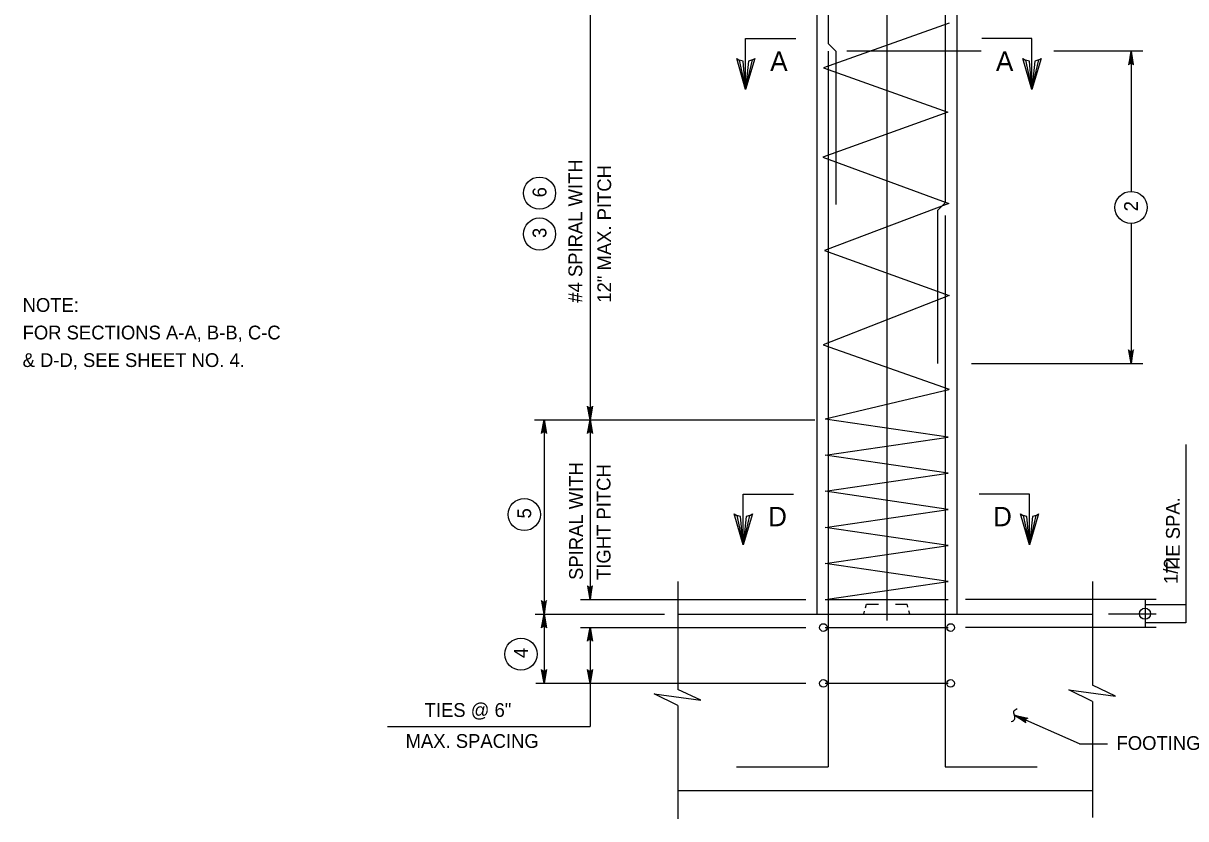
# Model space of a CAD drawing. Extents: x 646165 to 651486, y 296916 to 299292.
# Drawn here: x 648585.6 to 648838.6, y 297806.4 to 297979.6 of the extents above; entities that cross this region are included whole.
import ezdxf

# ---------------------------------------------------------------- set-up
doc = ezdxf.new("R2010")
doc.units = 0
for name, color, linetype in [('1', 7, 'Continuous'), ('50', 7, 'Continuous'), ('51', 7, 'Continuous'), ('52', 7, 'Continuous'), ('53', 7, 'Continuous'), ('54', 7, 'Continuous'), ('57', 7, 'Continuous')]:
    doc.layers.add(name, color=color, linetype=linetype)

msp = doc.modelspace()

# ---------------------------------------------------------------- linework, layer by layer
at = {"layer": '1'}
for p, q in [((648742.83, 297965.16), (648742.83, 297976.23)), ((648742.83, 297976.23), (648753.76, 297976.23)), ((648805.15, 297976.23), (648794.23, 297976.23)), ((648805.15, 297965.16), (648805.15, 297976.23)), ((648742.3, 297877.08), (648753.22, 297877.08)), ((648742.3, 297866.01), (648742.3, 297877.08)), ((648804.62, 297877.08), (648793.69, 297877.08)), ((648804.62, 297866.01), (648804.62, 297877.08))]:
    msp.add_line(p, q, dxfattribs=at)
for points in [[(648744.3, 297971.58), (648743.46, 297971.34), (648742.83, 297965.16), (648744.3, 297971.58), (648744.82, 297971.91), (648742.83, 297965.16), (648742.27, 297971.34), (648741.44, 297971.56), (648742.83, 297965.16), (648740.88, 297971.91), (648741.44, 297971.56)], [(648806.62, 297971.58), (648805.77, 297971.34), (648805.15, 297965.16), (648806.62, 297971.58), (648807.14, 297971.91), (648805.15, 297965.16), (648804.59, 297971.34), (648803.76, 297971.56), (648805.15, 297965.16), (648803.2, 297971.91), (648803.76, 297971.56)], [(648743.77, 297872.43), (648742.92, 297872.19), (648742.3, 297866.01), (648743.77, 297872.43), (648744.29, 297872.76), (648742.3, 297866.01), (648741.74, 297872.19), (648740.91, 297872.41), (648742.3, 297866.01), (648740.35, 297872.76), (648740.91, 297872.41)], [(648806.09, 297872.43), (648805.24, 297872.19), (648804.62, 297866.01), (648806.09, 297872.43), (648806.6, 297872.76), (648804.62, 297866.01), (648804.06, 297872.19), (648803.22, 297872.41), (648804.62, 297866.01), (648802.67, 297872.76), (648803.22, 297872.41)]]:
    msp.add_lwpolyline(points, dxfattribs=at)
at = {"layer": '50'}
msp.add_line((648773.54, 298034.59), (648773.54, 297849.57), dxfattribs=at)
at = {"layer": '51'}
for p, q in [((648758.31, 298027.15), (648758.31, 297850.9)), ((648788.77, 298027.15), (648788.77, 297850.9)), ((648768.91, 297852.34), (648769.11, 297853.1)), ((648769.11, 297853.1), (648771.75, 297853.1)), ((648775.48, 297853.1), (648777.98, 297853.1)), ((648778.15, 297852.43), (648777.98, 297853.1)), ((648728.08, 297850.9), (648818.35, 297850.9)), ((648768.54, 297850.9), (648768.71, 297851.57)), ((648778.54, 297850.9), (648778.34, 297851.68)), ((648728.08, 297812.57), (648818.35, 297812.57))]:
    msp.add_line(p, q, dxfattribs=at)
at = {"layer": '52'}
for p, q in [((648708.95, 297985.72), (648708.95, 297893.24)), ((648794.08, 297973.48), (648764.83, 297973.48)), ((648829.26, 297973.48), (648809.89, 297973.48)), ((648826.72, 297973.48), (648826.72, 297942.98)), ((648826.72, 297935.98), (648826.72, 297905.48)), ((648791.99, 297905.48), (648829.26, 297905.48)), ((648696.83, 297893.24), (648757.9, 297893.24)), ((648698.95, 297893.24), (648698.95, 297850.9)), ((648708.95, 297893.24), (648708.95, 297854.14)), ((648838.62, 297887.9), (648838.62, 297849.06)), ((648728.08, 297858.06), (648728.08, 297834.53)), ((648818.35, 297858.06), (648818.35, 297835.45)), ((648706.86, 297854.14), (648755.95, 297854.14)), ((648832.2, 297854.14), (648790.66, 297854.14)), ((648829.82, 297854.14), (648829.82, 297848.03)), ((648838.62, 297852.94), (648829.9, 297852.94)), ((648697.01, 297850.9), (648725.16, 297850.9)), ((648698.95, 297850.9), (648698.95, 297835.9)), ((648832.2, 297850.9), (648821.81, 297850.9)), ((648706.86, 297848.03), (648755.95, 297848.03)), ((648708.95, 297848.03), (648708.95, 297826.49)), ((648832.2, 297848.03), (648790.66, 297848.03)), ((648838.62, 297849.06), (648829.9, 297849.06)), ((648697.15, 297835.9), (648755.95, 297835.9)), ((648728.08, 297831.01), (648728.08, 297806.39)), ((648818.35, 297831.93), (648818.35, 297806.68)), ((648815.49, 297822.72), (648801.32, 297828.95)), ((648664.84, 297826.49), (648708.95, 297826.49)), ((648815.49, 297822.72), (648821.58, 297822.72))]:
    msp.add_line(p, q, dxfattribs=at)
for points in [[(648826.72, 297973.48), (648826.16, 297970.5), (648826.24, 297970.61), (648826.32, 297970.73), (648826.42, 297970.79), (648826.52, 297970.85), (648826.62, 297970.86), (648826.72, 297970.88), (648826.82, 297970.86), (648826.92, 297970.85), (648827.02, 297970.79), (648827.12, 297970.73), (648827.2, 297970.61), (648827.28, 297970.5), (648826.72, 297973.48), (648827.2, 297970.61), (648827.12, 297970.73), (648826.72, 297973.48), (648827.02, 297970.79), (648826.92, 297970.85), (648826.72, 297973.48), (648826.82, 297970.86), (648826.72, 297970.88), (648826.72, 297973.48), (648826.62, 297970.86), (648826.52, 297970.85), (648826.72, 297973.48), (648826.42, 297970.79), (648826.32, 297970.73), (648826.72, 297973.48), (648826.24, 297970.61)], [(648826.72, 297905.48), (648827.28, 297908.46), (648827.2, 297908.35), (648827.12, 297908.23), (648827.02, 297908.17), (648826.92, 297908.11), (648826.82, 297908.1), (648826.72, 297908.08), (648826.62, 297908.1), (648826.52, 297908.11), (648826.42, 297908.17), (648826.32, 297908.23), (648826.24, 297908.35), (648826.16, 297908.46), (648826.72, 297905.48), (648826.24, 297908.35), (648826.32, 297908.23), (648826.72, 297905.48), (648826.42, 297908.17), (648826.52, 297908.11), (648826.72, 297905.48), (648826.62, 297908.1), (648826.72, 297908.08), (648826.72, 297905.48), (648826.82, 297908.1), (648826.92, 297908.11), (648826.72, 297905.48), (648827.02, 297908.17), (648827.12, 297908.23), (648826.72, 297905.48), (648827.2, 297908.35)], [(648708.95, 297893.24), (648708.39, 297896.22), (648708.47, 297896.1), (648708.55, 297895.99), (648708.65, 297895.93), (648708.75, 297895.87), (648708.85, 297895.85), (648708.95, 297895.84), (648709.05, 297895.85), (648709.15, 297895.87), (648709.25, 297895.93), (648709.35, 297895.99), (648709.43, 297896.1), (648709.51, 297896.22), (648708.95, 297893.24), (648709.43, 297896.1), (648709.35, 297895.99), (648708.95, 297893.24), (648709.25, 297895.93), (648709.15, 297895.87), (648708.95, 297893.24), (648709.05, 297895.85), (648708.95, 297895.84), (648708.95, 297893.24), (648708.85, 297895.85), (648708.75, 297895.87), (648708.95, 297893.24), (648708.65, 297895.93), (648708.55, 297895.99), (648708.95, 297893.24), (648708.47, 297896.1)], [(648698.95, 297893.24), (648699.51, 297890.25), (648699.43, 297890.37), (648699.35, 297890.48), (648699.25, 297890.54), (648699.15, 297890.6), (648699.05, 297890.62), (648698.95, 297890.64), (648698.85, 297890.62), (648698.75, 297890.6), (648698.65, 297890.54), (648698.55, 297890.48), (648698.47, 297890.37), (648698.39, 297890.25), (648698.95, 297893.24), (648698.47, 297890.37), (648698.55, 297890.48), (648698.95, 297893.24), (648698.65, 297890.54), (648698.75, 297890.6), (648698.95, 297893.24), (648698.85, 297890.62), (648698.95, 297890.64), (648698.95, 297893.24), (648699.05, 297890.62), (648699.15, 297890.6), (648698.95, 297893.24), (648699.25, 297890.54), (648699.35, 297890.48), (648698.95, 297893.24), (648699.43, 297890.37)], [(648708.95, 297893.24), (648709.51, 297890.25), (648709.43, 297890.37), (648709.35, 297890.48), (648709.25, 297890.54), (648709.15, 297890.6), (648709.05, 297890.62), (648708.95, 297890.64), (648708.85, 297890.62), (648708.75, 297890.6), (648708.65, 297890.54), (648708.55, 297890.48), (648708.47, 297890.37), (648708.39, 297890.25), (648708.95, 297893.24), (648708.47, 297890.37), (648708.55, 297890.48), (648708.95, 297893.24), (648708.65, 297890.54), (648708.75, 297890.6), (648708.95, 297893.24), (648708.85, 297890.62), (648708.95, 297890.64), (648708.95, 297893.24), (648709.05, 297890.62), (648709.15, 297890.6), (648708.95, 297893.24), (648709.25, 297890.54), (648709.35, 297890.48), (648708.95, 297893.24), (648709.43, 297890.37)], [(648708.95, 297854.14), (648709.51, 297857.13), (648709.43, 297857.01), (648709.35, 297856.9), (648709.25, 297856.84), (648709.15, 297856.78), (648709.05, 297856.76), (648708.95, 297856.74), (648708.85, 297856.76), (648708.75, 297856.78), (648708.65, 297856.84), (648708.55, 297856.9), (648708.47, 297857.01), (648708.39, 297857.13), (648708.95, 297854.14), (648708.47, 297857.01), (648708.55, 297856.9), (648708.95, 297854.14), (648708.65, 297856.84), (648708.75, 297856.78), (648708.95, 297854.14), (648708.85, 297856.76), (648708.95, 297856.74), (648708.95, 297854.14), (648709.05, 297856.76), (648709.15, 297856.78), (648708.95, 297854.14), (648709.25, 297856.84), (648709.35, 297856.9), (648708.95, 297854.14), (648709.43, 297857.01)], [(648698.95, 297850.9), (648699.51, 297853.88), (648699.43, 297853.77), (648699.35, 297853.65), (648699.25, 297853.59), (648699.15, 297853.53), (648699.05, 297853.52), (648698.95, 297853.5), (648698.85, 297853.52), (648698.75, 297853.53), (648698.65, 297853.59), (648698.55, 297853.65), (648698.47, 297853.77), (648698.39, 297853.88), (648698.95, 297850.9), (648698.47, 297853.77), (648698.55, 297853.65), (648698.95, 297850.9), (648698.65, 297853.59), (648698.75, 297853.53), (648698.95, 297850.9), (648698.85, 297853.52), (648698.95, 297853.5), (648698.95, 297850.9), (648699.05, 297853.52), (648699.15, 297853.53), (648698.95, 297850.9), (648699.25, 297853.59), (648699.35, 297853.65), (648698.95, 297850.9), (648699.43, 297853.77)], [(648698.95, 297850.9), (648699.51, 297847.92), (648699.43, 297848.03), (648699.35, 297848.15), (648699.25, 297848.21), (648699.15, 297848.27), (648699.05, 297848.28), (648698.95, 297848.3), (648698.85, 297848.28), (648698.75, 297848.27), (648698.65, 297848.21), (648698.55, 297848.15), (648698.47, 297848.03), (648698.39, 297847.92), (648698.95, 297850.9), (648698.47, 297848.03), (648698.55, 297848.15), (648698.95, 297850.9), (648698.65, 297848.21), (648698.75, 297848.27), (648698.95, 297850.9), (648698.85, 297848.28), (648698.95, 297848.3), (648698.95, 297850.9), (648699.05, 297848.28), (648699.15, 297848.27), (648698.95, 297850.9), (648699.25, 297848.21), (648699.35, 297848.15), (648698.95, 297850.9), (648699.43, 297848.03)], [(648708.95, 297848.03), (648709.51, 297845.05), (648709.43, 297845.16), (648709.35, 297845.28), (648709.25, 297845.34), (648709.15, 297845.39), (648709.05, 297845.41), (648708.95, 297845.43), (648708.85, 297845.41), (648708.75, 297845.39), (648708.65, 297845.34), (648708.55, 297845.28), (648708.47, 297845.16), (648708.39, 297845.05), (648708.95, 297848.03), (648708.47, 297845.16), (648708.55, 297845.28), (648708.95, 297848.03), (648708.65, 297845.34), (648708.75, 297845.39), (648708.95, 297848.03), (648708.85, 297845.41), (648708.95, 297845.43), (648708.95, 297848.03), (648709.05, 297845.41), (648709.15, 297845.39), (648708.95, 297848.03), (648709.25, 297845.34), (648709.35, 297845.28), (648708.95, 297848.03), (648709.43, 297845.16)], [(648698.95, 297835.9), (648698.39, 297838.88), (648698.47, 297838.77), (648698.55, 297838.65), (648698.65, 297838.59), (648698.75, 297838.53), (648698.85, 297838.52), (648698.95, 297838.5), (648699.05, 297838.52), (648699.15, 297838.53), (648699.25, 297838.59), (648699.35, 297838.65), (648699.43, 297838.77), (648699.51, 297838.88), (648698.95, 297835.9), (648699.43, 297838.77), (648699.35, 297838.65), (648698.95, 297835.9), (648699.25, 297838.59), (648699.15, 297838.53), (648698.95, 297835.9), (648699.05, 297838.52), (648698.95, 297838.5), (648698.95, 297835.9), (648698.85, 297838.52), (648698.75, 297838.53), (648698.95, 297835.9), (648698.65, 297838.59), (648698.55, 297838.65), (648698.95, 297835.9), (648698.47, 297838.77)], [(648708.95, 297835.9), (648708.39, 297838.88), (648708.47, 297838.77), (648708.55, 297838.65), (648708.65, 297838.59), (648708.75, 297838.53), (648708.85, 297838.52), (648708.95, 297838.5), (648709.05, 297838.52), (648709.15, 297838.53), (648709.25, 297838.59), (648709.35, 297838.65), (648709.43, 297838.77), (648709.51, 297838.88), (648708.95, 297835.9), (648709.43, 297838.77), (648709.35, 297838.65), (648708.95, 297835.9), (648709.25, 297838.59), (648709.15, 297838.53), (648708.95, 297835.9), (648709.05, 297838.52), (648708.95, 297838.5), (648708.95, 297835.9), (648708.85, 297838.52), (648708.75, 297838.53), (648708.95, 297835.9), (648708.65, 297838.59), (648708.55, 297838.65), (648708.95, 297835.9), (648708.47, 297838.77)], [(648818.35, 297831.93), (648813.16, 297834.47), (648823.31, 297833.09), (648818.35, 297835.45)], [(648728.08, 297831.01), (648722.89, 297833.55), (648733.04, 297832.17), (648728.08, 297834.53)], [(648801.32, 297828.95), (648804.27, 297828.26), (648804, 297828.21), (648803.81, 297828.07), (648803.7, 297827.9), (648803.65, 297827.71), (648803.67, 297827.48), (648803.82, 297827.24), (648801.32, 297828.95), (648803.67, 297827.48), (648803.65, 297827.71), (648801.32, 297828.95), (648803.7, 297827.9), (648803.81, 297828.07), (648801.32, 297828.95), (648804, 297828.21)]]:
    msp.add_lwpolyline(points, dxfattribs=at)
for centre in [(648697.96, 297942.6), (648826.72, 297939.48), (648697.96, 297933.68), (648694.64, 297872.61), (648693.92, 297842.22)]:
    msp.add_circle(centre, 3.5, dxfattribs=at)
msp.add_spline([(648800.66, 297827.54), (648801.43, 297828.14), (648801.2, 297829.77), (648801.92, 297830.38)], degree=3, dxfattribs=at)
at = {"layer": '54'}
for p, q in [((648760.81, 298050.68), (648760.81, 297975.15)), ((648786.27, 298050.68), (648786.27, 297940.48)), ((648762.47, 297973.48), (648760.81, 297975.15)), ((648760.81, 297973.48), (648760.81, 297817.68)), ((648762.47, 297973.48), (648762.47, 297940.15)), ((648784.61, 297938.81), (648786.27, 297940.48)), ((648784.61, 297938.81), (648784.61, 297905.48)), ((648786.27, 297937.71), (648786.27, 297817.68)), ((648786.94, 297889.45), (648760.14, 297893.38)), ((648760.14, 297885.53), (648786.94, 297889.46)), ((648786.94, 297881.6), (648760.14, 297885.53)), ((648760.14, 297877.67), (648786.94, 297881.6)), ((648786.94, 297873.74), (648760.14, 297877.67)), ((648760.14, 297869.81), (648786.94, 297873.74)), ((648786.94, 297865.88), (648760.14, 297869.81)), ((648760.14, 297861.95), (648786.94, 297865.88)), ((648786.94, 297858.02), (648760.14, 297861.95)), ((648760.14, 297854.14), (648786.94, 297858.02)), ((648760.14, 297854.14), (648786.94, 297854.14)), ((648760.14, 297848.03), (648786.94, 297848.03)), ((648760.14, 297835.9), (648786.94, 297835.9)), ((648740.81, 297817.68), (648760.81, 297817.68)), ((648786.27, 297817.68), (648806.28, 297817.68))]:
    msp.add_line(p, q, dxfattribs=at)
msp.add_circle((648829.75, 297851.02), 1.21, dxfattribs=at)
at = {"layer": '57'}
for p, q in [((648787.16, 297979.57), (648759.75, 297969.87)), ((648759.75, 297969.87), (648786.81, 297960.25)), ((648786.81, 297960.25), (648759.64, 297950.43)), ((648759.64, 297950.43), (648787.04, 297940.3)), ((648787.04, 297940.3), (648759.98, 297930.07)), ((648759.98, 297930.07), (648787.16, 297920.34)), ((648787.16, 297920.34), (648759.72, 297909.56)), ((648759.72, 297909.56), (648787.1, 297899.92)), ((648787.04, 297899.79), (648760.14, 297893.38))]:
    msp.add_line(p, q, dxfattribs=at)
for centre in [(648759.75, 297848.02), (648787.43, 297848.02), (648759.75, 297835.85), (648787.43, 297835.85)]:
    msp.add_circle(centre, 0.837, dxfattribs=at)

# ---------------------------------------------------------------- texts
at = {"layer": '1'}
for s, p in [('A', (648748.18, 297969.21)), ('A', (648797.32, 297969.21)), ('D', (648747.72, 297870.06)), ('D', (648796.69, 297870.06))]:
    msp.add_text(s, height=4.23, dxfattribs=at).set_placement(p)
at = {"layer": '53'}
for s, p in [('#4 SPIRAL WITH', (648707.25, 297918.74)), ('12" MAX. PITCH', (648713.55, 297918.74)), ('6', (648699.46, 297941.67)), ('2', (648828.22, 297938.63)), ('3', (648699.46, 297932.83)), ('SPIRAL WITH', (648707.41, 297858.38)), ('TIGHT PITCH', (648713.41, 297858.38)), ('   TIE SPA.', (648837.33, 297856.53)), ('5', (648696.14, 297871.76)), ('1/2', (648836.87, 297857.5)), ('4', (648695.42, 297841.37))]:
    msp.add_text(s, height=3, rotation=90, dxfattribs=at).set_placement(p)
for s, p in [('NOTE:', (648585.44, 297916.74)), ('FOR SECTIONS A-A, B-B, C-C', (648585.44, 297910.74)), ('& D-D, SEE SHEET NO. 4.', (648585.44, 297904.74)), ('TIES @ 6"', (648672.95, 297828.56)), ('MAX. SPACING', (648668.81, 297821.81)), ('FOOTING', (648823.56, 297821.37))]:
    msp.add_text(s, height=3, dxfattribs=at).set_placement(p)

doc.saveas('drawing.dxf')
